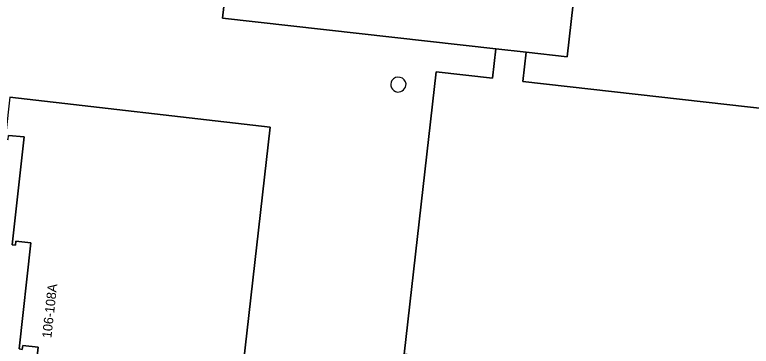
# Model space of a CAD drawing. Extents: x 161385 to 162589, y 388479 to 389756.
# Drawn here: x 162384.5 to 162463, y 388696.1 to 388731.4 of the extents above; entities that cross this region are included whole.
import ezdxf

# ---------------------------------------------------------------- set-up
doc = ezdxf.new("R2010")
doc.units = 0
for name, color, linetype in [('IMGEO_Erf', 7, 'Continuous'), ('IMGEO_Opslagtank', 7, 'Continuous'), ('IMGEO_Pand', 7, 'Continuous'), ('IMGEO_Pand_nummerreeks', 7, 'Continuous')]:
    doc.layers.add(name, color=color, linetype=linetype)

msp = doc.modelspace()

# ---------------------------------------------------------------- linework, layer by layer
at = {"layer": 'IMGEO_Erf'}
for points in [[(162383.967, 388722.64), (162411.707, 388719.457), (162406.76, 388675.873), (162412.776, 388675.396), (162420.122, 388674.813), (162420.461, 388674.786), (162446.489, 388672.997), (162447.18, 388679), (162448.384, 388678.861), (162448.49, 388679.822), (162449.227, 388686.456), (162448.051, 388686.549), (162448.713, 388692.673), (162448.008, 388692.753), (162425.971, 388695.283), (162429.384, 388725.33), (162435.4, 388724.653), (162435.751, 388727.776), (162406.633, 388731.063), (162412.095, 388778.923)], [(162446.098, 388751.105), (162443.362, 388726.917), (162438.974, 388727.412), (162438.622, 388724.29), (162491.877, 388718.298), (162493.83, 388723.458), (162495.067, 388734.36)], [(162379.117, 388678.821), (162384.504, 388678.222), (162386.947, 388677.951), (162387.452, 388682.311), (162385.802, 388682.494), (162385.755, 388682.067), (162385.427, 388682.103), (162385.766, 388685.174), (162386.965, 388696.018), (162385.325, 388696.199), (162385.279, 388695.782), (162384.951, 388695.818), (162386.201, 388707.129), (162384.591, 388707.307), (162384.544, 388706.88), (162384.216, 388706.916), (162385.484, 388718.406), (162383.83, 388718.549)]]:
    msp.add_lwpolyline(points, dxfattribs=at)
for centre, radius, start, end in [((162425.353, 388723.894), 0.867, 9.92019, 142.46239), ((162425.404, 388724.006), 0.848, 150.65012, 260.22323), ((162425.268, 388724.112), 0.941, 269.48482, 355.79307)]:
    msp.add_arc(centre, radius, start, end, dxfattribs=at)
at = {"layer": 'IMGEO_Opslagtank'}
for centre, radius, start, end in [((162425.353, 388723.894), 0.867, 9.92019, 142.46239), ((162425.404, 388724.006), 0.848, 150.65012, 260.22323), ((162425.268, 388724.112), 0.941, 269.48482, 355.79307)]:
    msp.add_arc(centre, radius, start, end, dxfattribs=at)
at = {"layer": 'IMGEO_Pand'}
for points in [[(162446.744, 388775.005), (162446.92, 388776.723), (162446.311, 388776.801), (162446.824, 388781.26), (162447.432, 388781.205), (162447.5, 388781.959), (162445.494, 388782.197), (162445.411, 388781.558), (162440.936, 388782.073), (162441.007, 388782.699), (162440.896, 388782.752), (162414.734, 388785.722), (162413.925, 388778.721), (162412.095, 388778.923), (162406.633, 388731.063), (162435.751, 388727.776), (162438.974, 388727.412), (162443.362, 388726.917), (162446.098, 388751.105), (162444.021, 388751.356)], [(162411.707, 388719.457), (162383.967, 388722.64), (162383.521, 388718.755), (162383.498, 388718.557), (162383.453, 388718.159), (162383.781, 388718.121), (162383.83, 388718.549), (162385.484, 388718.406), (162384.216, 388706.916), (162384.544, 388706.88), (162384.591, 388707.307), (162386.201, 388707.129), (162384.951, 388695.818), (162385.279, 388695.782), (162385.325, 388696.199), (162386.965, 388696.018), (162385.766, 388685.174), (162385.427, 388682.103), (162385.755, 388682.067), (162385.802, 388682.494), (162387.452, 388682.311), (162386.947, 388677.951), (162406.736, 388675.658), (162406.76, 388675.873)]]:
    msp.add_lwpolyline(points, close=True, dxfattribs=at)
msp.add_lwpolyline([(162491.877, 388718.298), (162438.622, 388724.29), (162438.974, 388727.412), (162435.751, 388727.776), (162435.4, 388724.653), (162429.384, 388725.33), (162425.971, 388695.283), (162448.008, 388692.753), (162448.713, 388692.673), (162448.051, 388686.549), (162449.227, 388686.456), (162448.49, 388679.822), (162448.384, 388678.861), (162447.18, 388679), (162446.489, 388672.997)], dxfattribs=at)

# ---------------------------------------------------------------- texts
at = {"layer": 'IMGEO_Pand_nummerreeks'}
msp.add_text('106-108A', height=1, rotation=83.69195, dxfattribs=at).set_placement((162388.375, 388696.939))

doc.saveas('drawing.dxf')
